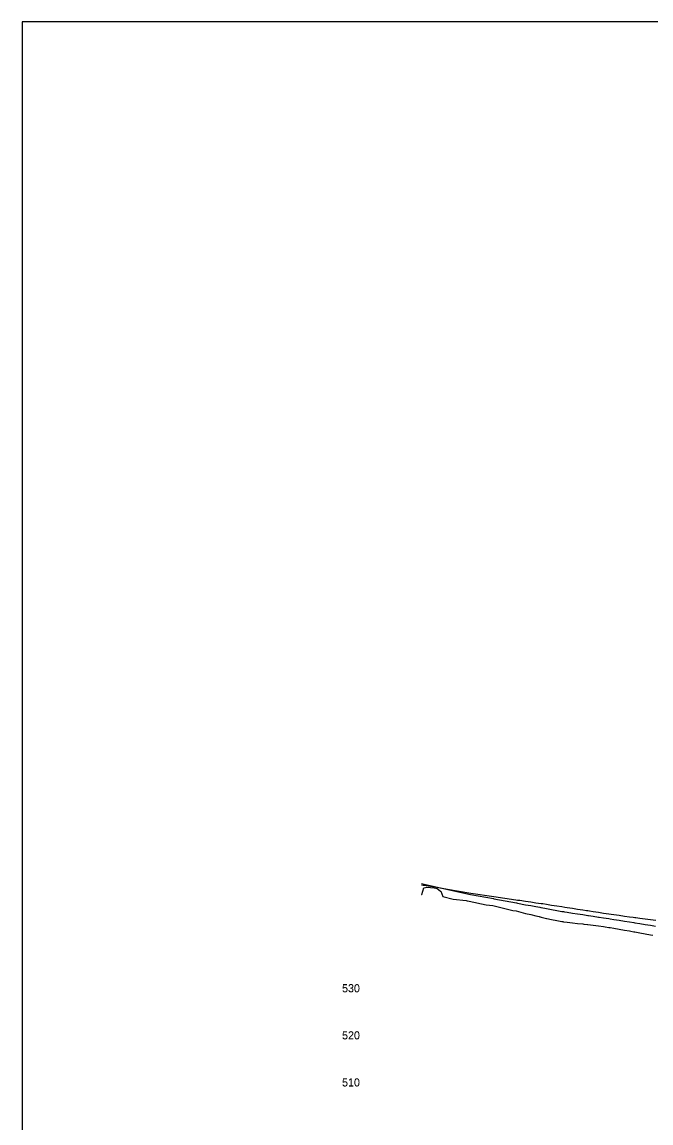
# Model space of a CAD drawing. Extents: x 2167726 to 2171326, y 1079832 to 1082032.
# Drawn here: x 2167726 to 2168394, y 1080863 to 1082032 of the extents above; entities that cross this region are included whole.
import ezdxf

# ---------------------------------------------------------------- set-up
doc = ezdxf.new("R2010")
doc.units = 0
for name, color, linetype in [('BR_EXIST_GROUND_LT', 7, 'Continuous'), ('BR_EXIST_GROUND_RT', 7, 'Continuous'), ('RD_DDB_ElevTX', 7, 'Continuous'), ('RD_DDB_Profile_EX', 7, 'Continuous'), ('RD_SHT_IplotShp', 7, 'Continuous')]:
    doc.layers.add(name, color=color, linetype=linetype)

msp = doc.modelspace()

# ---------------------------------------------------------------- linework, layer by layer
at = {"layer": 'BR_EXIST_GROUND_LT'}
msp.add_lwpolyline([(2168150.2, 1081115.7), (2168151.9, 1081115.4), (2168152.7, 1081115.3), (2168164.3, 1081113.5), (2168177.8, 1081111.2), (2168202.6, 1081106.9), (2168227, 1081103.3), (2168250.4, 1081099.8), (2168252.3, 1081099.4), (2168252.7, 1081099.4), (2168254.7, 1081099.3), (2168260.8, 1081098.4), (2168266.3, 1081097.5), (2168271.8, 1081096.7), (2168277.4, 1081095.9), (2168278.9, 1081095.7), (2168282.9, 1081095.1), (2168288.4, 1081094.2), (2168293.9, 1081093.4), (2168299.4, 1081092.6), (2168302.3, 1081092.1), (2168304.9, 1081091.7), (2168310.5, 1081090.9), (2168316, 1081090), (2168321.5, 1081089.1), (2168325.5, 1081088.5), (2168327, 1081088.3), (2168328.7, 1081088.1), (2168332.5, 1081087.4), (2168338.1, 1081086.6), (2168343.6, 1081085.7), (2168349.1, 1081084.8), (2168351.6, 1081084.4), (2168354.6, 1081084), (2168360.1, 1081083.3), (2168365.6, 1081082.5), (2168371.2, 1081081.8), (2168374.9, 1081081.3), (2168376.7, 1081081.1), (2168377.8, 1081081), (2168382.2, 1081080.4), (2168387.7, 1081079.7), (2168393.2, 1081078.9), (2168398.9, 1081078.2)], dxfattribs=at)
at = {"layer": 'BR_EXIST_GROUND_RT'}
msp.add_lwpolyline([(2168150.2, 1081105.5), (2168150.5, 1081105.4), (2168152.6, 1081112.4), (2168153, 1081112.5), (2168156, 1081113.1), (2168163.8, 1081112.6), (2168166.9, 1081111.9), (2168170.5, 1081109), (2168170.9, 1081108.8), (2168172.9, 1081103.4), (2168184, 1081100.3), (2168197.7, 1081099), (2168198.8, 1081098.7), (2168200.8, 1081098.5), (2168218.8, 1081094.4), (2168225.8, 1081093.6), (2168247.2, 1081088.5), (2168250.7, 1081088), (2168260.8, 1081085.4), (2168266.3, 1081084), (2168271.8, 1081082.7), (2168275.2, 1081081.9), (2168275.8, 1081081.8), (2168276.2, 1081081.7), (2168277.4, 1081081.4), (2168282.9, 1081080), (2168283.4, 1081079.9), (2168288.4, 1081078.9), (2168293.9, 1081077.8), (2168299.4, 1081076.7), (2168300.2, 1081076.6), (2168300.9, 1081076.4), (2168301.3, 1081076.4), (2168304.9, 1081076), (2168310.5, 1081075.4), (2168316, 1081074.7), (2168321.5, 1081074.1), (2168322.7, 1081074), (2168326.5, 1081073.4), (2168327, 1081073.4), (2168332.5, 1081072.7), (2168338.1, 1081072), (2168343.6, 1081071.3), (2168345.3, 1081071.1), (2168349.1, 1081070.5), (2168350.6, 1081070.3), (2168354.6, 1081069.6), (2168360.1, 1081068.6), (2168365.6, 1081067.7), (2168371.2, 1081066.7), (2168372.4, 1081066.5), (2168375.7, 1081065.9), (2168376.7, 1081065.7), (2168382.2, 1081064.7), (2168387.7, 1081063.6), (2168393.2, 1081062.6), (2168395.9, 1081062.1)], dxfattribs=at)
at = {"layer": 'RD_DDB_Profile_EX'}
msp.add_lwpolyline([(2168150.2, 1081117), (2168152.9, 1081116.4), (2168153.2, 1081116.3), (2168178.2, 1081110.8), (2168202.1, 1081105.5), (2168226.7, 1081101), (2168227.1, 1081100.9), (2168251.2, 1081096.4), (2168252.1, 1081096.2), (2168260.8, 1081094.6), (2168266.3, 1081093.6), (2168271.8, 1081092.6), (2168275.8, 1081091.8), (2168277, 1081091.6), (2168277.4, 1081091.6), (2168282.9, 1081090.5), (2168288.4, 1081089.5), (2168293.9, 1081088.5), (2168299.4, 1081087.4), (2168300.9, 1081087.2), (2168302, 1081087), (2168302.5, 1081086.9), (2168304.9, 1081086.5), (2168310.5, 1081085.7), (2168316, 1081084.9), (2168321.5, 1081084), (2168327, 1081083.2), (2168327.5, 1081083.1), (2168332.5, 1081082.4), (2168338.1, 1081081.5), (2168338.9, 1081081.4), (2168343.6, 1081080.7), (2168349.1, 1081079.8), (2168350.7, 1081079.6), (2168354.6, 1081079), (2168360.1, 1081078.1), (2168365.6, 1081077.2), (2168371.2, 1081076.3), (2168375.7, 1081075.6), (2168376.7, 1081075.5), (2168382.2, 1081074.6), (2168387.7, 1081073.7), (2168393.2, 1081072.8), (2168398.7, 1081071.9)], dxfattribs=at)
at = {"layer": 'RD_SHT_IplotShp'}
msp.add_lwpolyline([(2167726.1, 1079832), (2171326.1, 1079832), (2171326.1, 1082032), (2167726.1, 1082032)], close=True, dxfattribs=at)

# ---------------------------------------------------------------- texts
at = {"layer": 'RD_DDB_ElevTX'}
for s, p in [('530', (2168065.9, 1081001.7)), ('530', (2168065.9, 1081001.5)), ('520', (2168065.9, 1080951.7)), ('520', (2168065.9, 1080951.5)), ('510', (2168065.9, 1080901.7)), ('510', (2168065.9, 1080901.5))]:
    msp.add_text(s, height=8.5, dxfattribs=at).set_placement(p)

doc.saveas('drawing.dxf')
